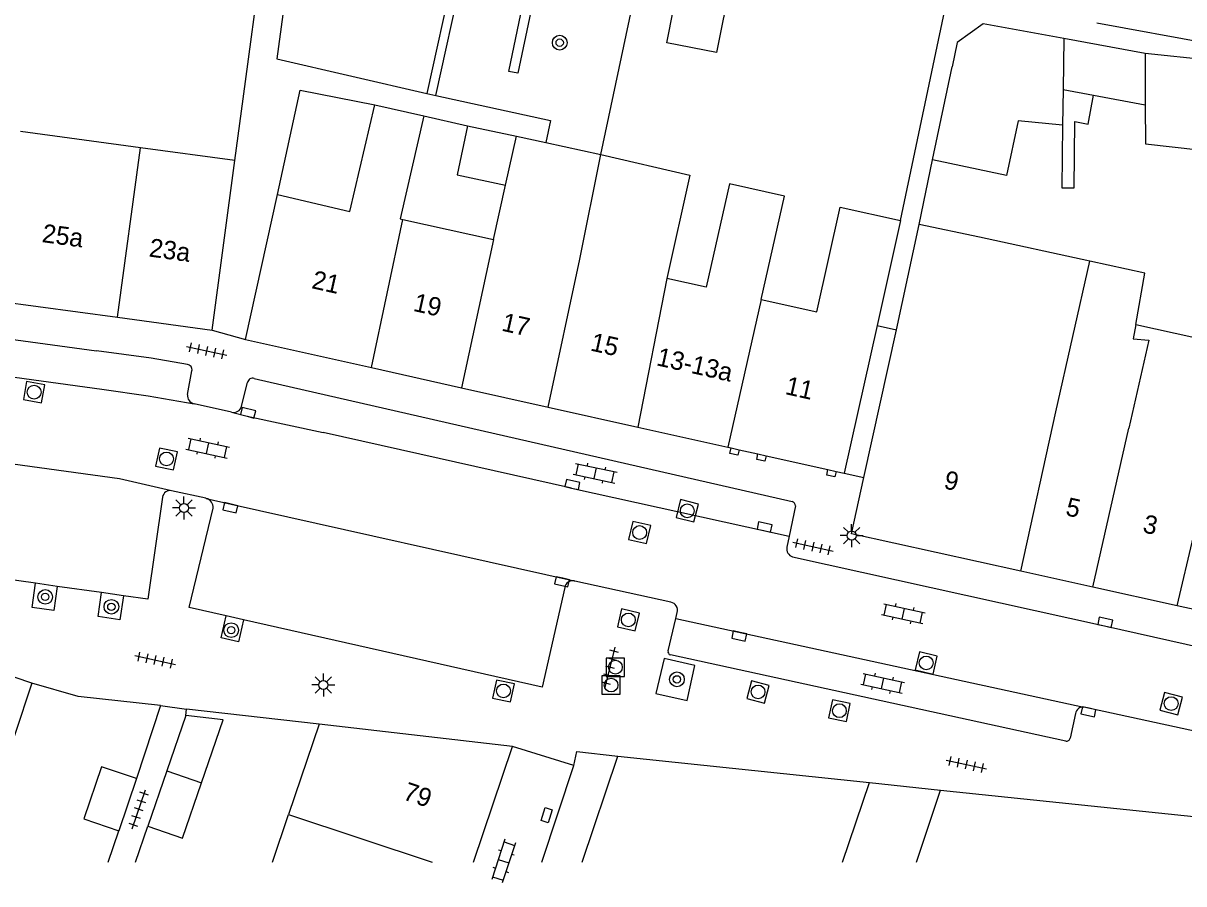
# Model space of a CAD drawing. Extents: x 132999 to 136000, y 398499 to 400501.
# Drawn here: x 133754.4 to 133817.5, y 398498.8 to 398545.6 of the extents above; entities that cross this region are included whole.
import ezdxf

# ---------------------------------------------------------------- set-up
doc = ezdxf.new("R2010")
doc.units = 0
for name, color, linetype in [('gg-afsc-erfafscheiding', 7, 'Continuous'), ('gg-afsc-hekwerk', 7, 'Continuous'), ('gg-afsc-muur', 7, 'Continuous'), ('gg-anno-huisnummerreeks BGT', 7, 'Continuous'), ('gg-bbg-bijgebouw', 7, 'Continuous'), ('gg-bbg-gedigitaliseerde bebouwing', 7, 'Continuous'), ('gg-bbg-gedigitaliseerde bebouwing onder overbouw', 7, 'Continuous'), ('gg-bbg-gedigitaliseerde bijgebouw', 7, 'Continuous'), ('gg-bbg-gedigitaliseerde overbouw', 7, 'Continuous'), ('gg-bbg-hoofdgebouw', 7, 'Continuous'), ('gg-bbg-luifel en loopbrug', 7, 'Continuous'), ('gg-bbg-pand overbouw', 7, 'Continuous'), ('gg-bbg-tussenscheiding', 7, 'Continuous'), ('gg-knt-verharding', 7, 'Continuous'), ('gg-knt-verharding nz', 7, 'Continuous'), ('gt-grn-groengrens', 7, 'Continuous'), ('gt-grn-weggrens', 7, 'Continuous'), ('gt-symb-boom', 7, 'Continuous'), ('gt-symb-klinker verharding', 7, 'Continuous'), ('gt-symb-kolk', 7, 'Continuous'), ('gt-symb-kolk center center', 7, 'Continuous'), ('gt-symb-lichtmast', 7, 'Continuous'), ('gt-symb-rioolschacht', 7, 'Continuous'), ('gt-symb-tegel verharding', 7, 'Continuous')]:
    doc.layers.add(name, color=color, linetype=linetype)

# ---------------------------------------------------------------- blocks, each defined once
blk = doc.blocks.new('gt0-BOOM')
at = {"layer": 'gt-symb-boom'}
for radius in [0.4, 0.2]:
    blk.add_circle((0, 0), radius, dxfattribs=at)
blk = doc.blocks.new('gt0-TEG1')
at = {"layer": 'gt-symb-tegel verharding'}
for p, q in [((-1.125, 0), (1.125, 0)), ((-0.9, -0.25), (-0.9, 0.25)), ((-0.45, -0.25), (-0.45, 0.25)), ((0, -0.25), (0, 0.25)), ((0.45, -0.25), (0.45, 0.25)), ((0.9, -0.25), (0.9, 0.25))]:
    blk.add_line(p, q, dxfattribs=at)
blk = doc.blocks.new('gt0-RS')
at = {"layer": 'gt-symb-rioolschacht'}
blk.add_lwpolyline([(-0.5, -0.5), (0.5, -0.5), (0.5, 0.5), (-0.5, 0.5)], close=True, dxfattribs=at)
blk.add_circle((0, 0), 0.375, dxfattribs=at)
blk = doc.blocks.new('gt0-KOLK')
at = {"layer": 'gt-symb-kolk'}
blk.add_lwpolyline([(0, 0), (0.375, 0), (0.375, 0.4), (-0.375, 0.4), (-0.375, 0), (0, 0)], dxfattribs=at)
blk = doc.blocks.new('gt0-KL1')
at = {"layer": 'gt-symb-klinker verharding'}
for p, q in [((-1.15, 0.3), (1.15, 0.3)), ((-1, -0.3), (-1, 0.3)), ((-0.5, 0.3), (-0.5, 0.45)), ((0, -0.3), (0, 0.3)), ((0.5, 0.3), (0.5, 0.45)), ((1, -0.3), (1, 0.3)), ((-1.15, -0.3), (1.15, -0.3)), ((-0.5, -0.45), (-0.5, -0.3)), ((0.5, -0.45), (0.5, -0.3))]:
    blk.add_line(p, q, dxfattribs=at)
blk = doc.blocks.new('gt0-LMAST')
at = {"layer": 'gt-symb-lichtmast'}
for p, q in [((-0.182, 0.173), (-0.447, 0.438)), ((-0.005, 0.246), (-0.005, 0.621)), ((0.172, 0.173), (0.437, 0.438)), ((-0.255, -0.004), (-0.63, -0.004)), ((-0.182, -0.181), (-0.447, -0.446)), ((-0.005, -0.254), (-0.005, -0.629)), ((0.437, -0.446), (0.172, -0.181)), ((0.245, -0.004), (0.62, -0.004))]:
    blk.add_line(p, q, dxfattribs=at)
blk.add_circle((-0.005, -0.004), 0.25, dxfattribs=at)
blk = doc.blocks.new('gt0-KOLKCC')
at = {"layer": 'gt-symb-kolk center center'}
blk.add_lwpolyline([(-0.375, 0.2), (0.375, 0.2), (0.375, -0.2), (-0.375, -0.2)], close=True, dxfattribs=at)

msp = doc.modelspace()

# ---------------------------------------------------------------- linework, layer by layer
at = {"layer": 'gg-afsc-erfafscheiding'}
for p, q in [((133785.848, 398538.479), (133788.011, 398548.694)), ((133802.141, 398534.88), (133804.709, 398547.134)), ((133812.811, 398545.642), (133819.826, 398544.351)), ((133803.143, 398534.665), (133803.88, 398538.181)), ((133761.902, 398508.507), (133760.593, 398504.543)), ((133763.284, 398507.975), (133763.315, 398508.313)), ((133759.054, 398500), (133759.631, 398501.701)), ((133760.549, 398500), (133761.208, 398501.943))]:
    msp.add_line(p, q, dxfattribs=at)
for points in [[(133765.944, 398538.153), (133766.393, 398541.509), (133767.437, 398549.211)], [(133768.258, 398536.304), (133769.488, 398541.979), (133773.557, 398541.183)]]:
    msp.add_lwpolyline(points, dxfattribs=at)
at = {"layer": 'gg-afsc-hekwerk'}
for p, q in [((133761.902, 398508.507), (133763.315, 398508.313)), ((133800.45, 398504.328), (133804.313, 398503.901))]:
    msp.add_line(p, q, dxfattribs=at)
at = {"layer": 'gg-afsc-muur'}
for p, q in [((133776.212, 398540.576), (133778.6, 398540.037)), ((133770.521, 398507.502), (133763.315, 398508.313))]:
    msp.add_line(p, q, dxfattribs=at)
msp.add_lwpolyline([(133761.902, 398508.507), (133757.421, 398508.992), (133754.914, 398509.721)], dxfattribs=at)
at = {"layer": 'gg-bbg-bijgebouw'}
for p, q in [((133763.284, 398507.975), (133762.246, 398504.959)), ((133784.826, 398500), (133786.769, 398505.747)), ((133786.769, 398505.747), (133800.45, 398504.328)), ((133762.246, 398504.959), (133761.208, 398501.943)), ((133760.593, 398504.543), (133759.631, 398501.701)), ((133798.989, 398500), (133800.45, 398504.328))]:
    msp.add_line(p, q, dxfattribs=at)
for points in [[(133764.133, 398504.313), (133765.303, 398507.728), (133763.284, 398507.975)], [(133760.593, 398504.543), (133758.699, 398505.184), (133757.737, 398502.342), (133759.631, 398501.701)], [(133761.208, 398501.943), (133763.099, 398501.292), (133764.133, 398504.313)]]:
    msp.add_lwpolyline(points, dxfattribs=at)
at = {"layer": 'gg-bbg-gedigitaliseerde bebouwing'}
for p, q in [((133760.816, 398538.843), (133754.295, 398539.721)), ((133765.944, 398538.153), (133760.816, 398538.843)), ((133785.848, 398538.479), (133790.686, 398537.36)), ((133764.71, 398528.931), (133765.944, 398538.153)), ((133790.686, 398537.36), (133789.428, 398531.737)), ((133780.001, 398533.844), (133780.664, 398536.81)), ((133775.08, 398534.945), (133780.001, 398533.844)), ((133802.141, 398534.88), (133800.867, 398529.179)), ((133801.923, 398528.943), (133803.143, 398534.665)), ((133814.922, 398529.225), (133818.147, 398528.527))]:
    msp.add_line(p, q, dxfattribs=at)
for points in [[(133776.212, 398540.576), (133774.932, 398534.979), (133775.08, 398534.945)], [(133794.556, 398530.59), (133795.827, 398536.211), (133792.839, 398536.879), (133791.568, 398531.258), (133789.428, 398531.737)], [(133794.556, 398530.59), (133797.579, 398529.914), (133798.854, 398535.615), (133802.141, 398534.88)], [(133812.432, 398532.678), (133806.434, 398533.975), (133803.143, 398534.665)], [(133814.922, 398529.225), (133815.427, 398532.031), (133812.432, 398532.678)]]:
    msp.add_lwpolyline(points, dxfattribs=at)
at = {"layer": 'gg-bbg-gedigitaliseerde bebouwing onder overbouw'}
for p, q in [((133800.867, 398529.179), (133799.07, 398521.141)), ((133800.148, 398520.903), (133801.923, 398528.943))]:
    msp.add_line(p, q, dxfattribs=at)
at = {"layer": 'gg-bbg-gedigitaliseerde bijgebouw'}
for p, q in [((133815.435, 398543.966), (133811.009, 398544.781)), ((133803.88, 398538.181), (133804.941, 398543.243)), ((133810.974, 398542.007), (133810.949, 398540.062)), ((133810.974, 398542.007), (133812.63, 398541.702)), ((133812.63, 398541.702), (133815.446, 398541.183))]:
    msp.add_line(p, q, dxfattribs=at)
for points in [[(133792.886, 398547.833), (133792.13, 398544.015), (133789.424, 398544.545), (133790.179, 398548.311)], [(133811.009, 398544.781), (133806.622, 398545.589), (133805.22, 398544.574), (133804.941, 398543.243)], [(133818.358, 398538.736), (133818.896, 398543.602), (133815.435, 398543.966)], [(133815.446, 398541.183), (133815.455, 398539.057), (133818.358, 398538.736)], [(133810.949, 398540.062), (133808.527, 398540.314), (133807.903, 398537.338), (133803.88, 398538.181)], [(133778.6, 398540.037), (133778.028, 398537.376), (133780.664, 398536.81)]]:
    msp.add_lwpolyline(points, dxfattribs=at)
at = {"layer": 'gg-bbg-gedigitaliseerde overbouw'}
msp.add_line((133800.867, 398529.179), (133801.923, 398528.943), dxfattribs=at)
at = {"layer": 'gg-bbg-hoofdgebouw'}
for p, q in [((133773.557, 398541.183), (133776.212, 398540.576)), ((133778.6, 398540.037), (133781.258, 398539.466)), ((133781.258, 398539.466), (133782.853, 398539.123)), ((133782.853, 398539.123), (133785.848, 398538.479)), ((133766.52, 398528.421), (133768.258, 398536.304)), ((133753.072, 398530.501), (133759.573, 398529.624)), ((133759.573, 398529.624), (133764.71, 398528.931)), ((133766.52, 398528.421), (133773.375, 398526.888)), ((133773.375, 398526.888), (133778.268, 398525.794)), ((133778.268, 398525.794), (133782.987, 398524.738)), ((133782.987, 398524.738), (133787.849, 398523.651)), ((133787.849, 398523.651), (133792.74, 398522.557)), ((133792.74, 398522.557), (133792.922, 398522.516)), ((133792.922, 398522.516), (133793.361, 398522.418)), ((133793.361, 398522.418), (133794.386, 398522.189)), ((133794.386, 398522.189), (133794.825, 398522.091)), ((133794.825, 398522.091), (133798.192, 398521.337)), ((133798.192, 398521.337), (133798.631, 398521.239)), ((133798.631, 398521.239), (133799.07, 398521.141)), ((133812.593, 398514.944), (133808.67, 398515.81)), ((133817.177, 398513.932), (133812.593, 398514.944)), ((133754.914, 398509.721), (133745.124, 398513.029)), ((133754.914, 398509.721), (133753.036, 398504.14)), ((133770.521, 398507.502), (133768.867, 398502.587)), ((133781.035, 398506.282), (133770.521, 398507.502)), ((133778.915, 398500), (133781.035, 398506.282)), ((133803, 398500), (133804.313, 398503.901)), ((133804.313, 398503.901), (133822.056, 398502.068)), ((133767.997, 398500), (133768.867, 398502.587))]:
    msp.add_line(p, q, dxfattribs=at)
for points in [[(133768.258, 398536.304), (133772.198, 398535.367), (133773.557, 398541.183)], [(133808.67, 398515.81), (133799.47, 398517.841), (133800.148, 398520.903)], [(133825.33, 398512.221), (133818.27, 398513.691), (133817.177, 398513.932)]]:
    msp.add_lwpolyline(points, dxfattribs=at)
at = {"layer": 'gg-bbg-luifel en loopbrug'}
msp.add_lwpolyline([(133810.949, 398540.062), (133810.907, 398536.665), (133811.578, 398536.656), (133811.623, 398540.265), (133812.341, 398540.132), (133812.63, 398541.702)], dxfattribs=at)
at = {"layer": 'gg-bbg-pand overbouw'}
msp.add_line((133799.07, 398521.141), (133800.148, 398520.903), dxfattribs=at)
at = {"layer": 'gg-bbg-tussenscheiding'}
for p, q in [((133811.009, 398544.781), (133810.974, 398542.007)), ((133815.435, 398543.966), (133815.446, 398541.183)), ((133780.664, 398536.81), (133781.258, 398539.466)), ((133759.573, 398529.624), (133760.816, 398538.843)), ((133773.375, 398526.888), (133775.08, 398534.945)), ((133780.001, 398533.844), (133778.268, 398525.794)), ((133810.582, 398524.473), (133812.432, 398532.678)), ((133789.428, 398531.737), (133787.849, 398523.651)), ((133794.556, 398530.59), (133792.74, 398522.557)), ((133808.67, 398515.81), (133810.582, 398524.473)), ((133812.593, 398514.944), (133814.559, 398523.594)), ((133817.177, 398513.932), (133819.205, 398522.588)), ((133762.246, 398504.959), (133764.133, 398504.313)), ((133768.867, 398502.587), (133776.669, 398500))]:
    msp.add_line(p, q, dxfattribs=at)
for points in [[(133782.987, 398524.738), (133784.709, 398532.792), (133785.848, 398538.479)], [(133814.922, 398529.225), (133814.782, 398528.449), (133815.646, 398528.373), (133814.559, 398523.594)]]:
    msp.add_lwpolyline(points, dxfattribs=at)
at = {"layer": 'gg-knt-verharding'}
for p, q in [((133776.382, 398541.793), (133776.87, 398541.683)), ((133763.377, 398525.415), (133763.611, 398526.71)), ((133767, 398526.29), (133796.246, 398519.609)), ((133766.315, 398524.782), (133766.642, 398526.074)), ((133765.769, 398524.458), (133763.727, 398524.923)), ((133764.373, 398519.781), (133762.509, 398520.194)), ((133764.373, 398519.781), (133764.39, 398519.777)), ((133796.423, 398519.368), (133796.084, 398517.714)), ((133796.084, 398517.714), (133795.961, 398517.115)), ((133756.283, 398514.989), (133755.11, 398515.155)), ((133758.702, 398514.648), (133756.283, 398514.989)), ((133784.435, 398515.277), (133784.396, 398515.286)), ((133789.654, 398514.131), (133784.435, 398515.277)), ((133759.885, 398514.481), (133758.702, 398514.648)), ((133766.416, 398513.175), (133765.478, 398513.387)), ((133789.498, 398511.491), (133789.916, 398513.248)), ((133789.916, 398513.248), (133789.992, 398513.567)), ((133811.127, 398506.577), (133789.631, 398511.259)), ((133811.653, 398508.07), (133811.354, 398506.729)), ((133826.534, 398505.282), (133812.111, 398508.423)), ((133784.384, 398505.246), (133781.035, 398506.282)), ((133782.63, 398500), (133784.384, 398505.246))]:
    msp.add_line(p, q, dxfattribs=at)
for points in [[(133782.245, 398549.718), (133769.355, 398551.993), (133768.22, 398543.678), (133776.382, 398541.793)], [(133776.87, 398541.683), (133783.109, 398540.316), (133782.853, 398539.123)], [(133720.867, 398531.313), (133721.073, 398532.895), (133758.42, 398527.801)], [(133763.366, 398527.06), (133761.397, 398527.395), (133758.42, 398527.801)], [(133793.361, 398522.418), (133793.296, 398522.125), (133792.856, 398522.224), (133792.922, 398522.516)], [(133755.11, 398515.155), (133746.922, 398516.31), (133747.725, 398522.032)], [(133794.825, 398522.091), (133794.759, 398521.798), (133794.32, 398521.896), (133794.386, 398522.189)], [(133798.631, 398521.239), (133798.565, 398520.946), (133798.126, 398521.045), (133798.192, 398521.337)], [(133762.015, 398519.846), (133761.206, 398514.295), (133759.885, 398514.481)], [(133765.478, 398513.387), (133763.459, 398513.842), (133764.76, 398519.238)], [(133796.261, 398516.597), (133813.224, 398512.839), (133826.382, 398509.897), (133827.455, 398509.674)], [(133756.283, 398514.989), (133756.097, 398513.673), (133754.925, 398513.843), (133755.11, 398515.155)], [(133783.885, 398514.929), (133782.65, 398509.516), (133766.416, 398513.175)], [(133759.885, 398514.481), (133759.7, 398513.173), (133758.518, 398513.346), (133758.702, 398514.648)], [(133766.416, 398513.175), (133766.147, 398511.982), (133765.207, 398512.184), (133765.478, 398513.387)], [(133789.289, 398511.063), (133788.836, 398509.163), (133790.541, 398508.78), (133790.951, 398510.682), (133789.289, 398511.063)], [(133784.384, 398505.246), (133784.534, 398506.002), (133786.769, 398505.747)]]:
    msp.add_lwpolyline(points, dxfattribs=at)
for centre, radius, start, end in [((133763.327, 398526.772), 0.29, 347.65134, 82.3327), ((133766.901, 398526.05), 0.26, 67.56084, 174.64868), ((133763.811, 398525.353), 0.439, 171.93122, 258.92351), ((133765.87, 398524.911), 0.464, 257.47953, 343.89081), ((133762.437, 398519.772), 0.428, 80.25882, 170.067), ((133764.267, 398519.296), 0.496, 353.25373, 75.68207), ((133796.18, 398519.375), 0.243, 358.27938, 74.3107), ((133796.392, 398517.019), 0.441, 167.38529, 252.76932), ((133784.317, 398514.854), 0.439, 79.66645, 170.21217), ((133789.564, 398513.694), 0.446, 343.50896, 78.35878), ((133789.685, 398511.444), 0.193, 166.0107, 253.63851), ((133812.059, 398508.017), 0.41, 82.74055, 172.50538), ((133811.172, 398506.755), 0.183, 255.66594, 351.94687)]:
    msp.add_arc(centre, radius, start, end, dxfattribs=at)
at = {"layer": 'gg-knt-verharding nz'}
for p, q in [((133741.118, 398528.107), (133758.721, 398525.714)), ((133784.257, 398520.335), (133770.746, 398523.352)), ((133784.257, 398520.335), (133796.084, 398517.714)), ((133789.916, 398513.248), (133812.111, 398508.423))]:
    msp.add_line(p, q, dxfattribs=at)
for points in [[(133758.721, 398525.714), (133761.228, 398525.345), (133763.727, 398524.923)], [(133765.769, 398524.458), (133766.614, 398524.237), (133770.746, 398523.352)], [(133762.509, 398520.194), (133759.683, 398520.831), (133749.505, 398522.227), (133747.32, 398522.55)], [(133764.39, 398519.777), (133765.74, 398519.461), (133784.396, 398515.286)]]:
    msp.add_lwpolyline(points, dxfattribs=at)
at = {"layer": 'gt-grn-groengrens'}
for points in [[(133782.737, 398549.631), (133781.332, 398542.896), (133780.842, 398542.998), (133782.245, 398549.718)], [(133776.87, 398541.683), (133778.297, 398548.2), (133777.809, 398548.306), (133776.382, 398541.793)]]:
    msp.add_lwpolyline(points, dxfattribs=at)
at = {"layer": 'gt-grn-weggrens'}
msp.add_line((133764.71, 398528.931), (133766.52, 398528.421), dxfattribs=at)

# ---------------------------------------------------------------- block references
at = {"layer": 'gt-symb-boom'}
for p in [(133783.607, 398544.557), (133755.636, 398514.418), (133759.232, 398513.879), (133765.744, 398512.609), (133789.98, 398509.933)]:
    msp.add_blockref('gt0-BOOM', p, dxfattribs=at)
at = {"layer": 'gt-symb-klinker verharding'}
for p, rotation in [((133764.476, 398522.508), -12.298855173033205), ((133785.536, 398521.141), -12.174751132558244), ((133802.286, 398513.502), -12.41077472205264), ((133801.165, 398509.718), -12.410774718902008), ((133780.554, 398500.048), -108.18126897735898)]:
    msp.add_blockref('gt0-KL1', p, dxfattribs=dict(at, rotation=rotation))
at = {"layer": 'gt-symb-kolk'}
for p, rotation in [((133766.614, 398524.237), -14.66187016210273), ((133784.257, 398520.335), -12.479071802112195), ((133765.74, 398519.461), 166.82507339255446), ((133794.702, 398518.02), -12.493796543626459), ((133783.774, 398515.428), 167.40904938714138), ((133813.224, 398512.839), -12.49379654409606), ((133793.413, 398512.487), 167.72939792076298), ((133812.398, 398508.36), 167.72151291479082)]:
    msp.add_blockref('gt0-KOLK', p, dxfattribs=dict(at, rotation=rotation))
at = {"layer": 'gt-symb-kolk center center', "rotation": -107.94556305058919}
msp.add_blockref('gt0-KOLKCC', (133782.897, 398502.551), dxfattribs=at)
at = {"layer": 'gt-symb-lichtmast'}
for p in [(133763.185, 398519.257), (133799.484, 398517.756), (133770.762, 398509.633)]:
    msp.add_blockref('gt0-LMAST', p, dxfattribs=at)
at = {"layer": 'gt-symb-rioolschacht'}
for p, rotation in [((133755.032, 398525.549), -9.96151659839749), ((133762.232, 398521.918), -101.95064726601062), ((133790.543, 398519.099), 165.78174773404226), ((133787.954, 398517.916), -12.938810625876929), ((133787.34, 398513.164), -12.827123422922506), ((133803.535, 398510.825), 166.47068167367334), ((133780.549, 398509.303), -12.062746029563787), ((133794.392, 398509.249), -14.952208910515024), ((133798.815, 398508.229), -12.015845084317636), ((133816.853, 398508.614), 165.49013525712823)]:
    msp.add_blockref('gt0-RS', p, dxfattribs=dict(at, rotation=rotation))
for p in [(133786.637, 398510.594), (133786.401, 398509.623)]:
    msp.add_blockref('gt0-RS', p, dxfattribs=at)
at = {"layer": 'gt-symb-tegel verharding'}
for p, rotation in [((133764.419, 398527.794), -12.29885516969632), ((133797.38, 398517.146), -12.410774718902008), ((133761.615, 398510.982), -12.29885516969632), ((133786.352, 398510.585), 76.06098564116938), ((133805.72, 398505.302), -12.410774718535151), ((133760.728, 398502.863), 71.45633066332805)]:
    msp.add_blockref('gt0-TEG1', p, dxfattribs=dict(at, rotation=rotation))

# ---------------------------------------------------------------- texts
at = {"layer": 'gg-anno-huisnummerreeks BGT'}
for s, rotation, p in [('25a', 352.3, (133755.425, 398533.716)), ('23a', 352.3, (133761.244, 398532.931)), ('21', 347.4, (133770.075, 398531.212)), ('19', 347.4, (133775.597, 398529.977)), ('17', 347.4, (133780.4, 398528.903)), ('15', 347.4, (133785.229, 398527.823)), ('13-13a', 347.4, (133788.818, 398527.02)), ('11', 347.4, (133795.82, 398525.454)), ('9', 347.5, (133804.445, 398520.327)), ('5', 347.5, (133811.064, 398518.866)), ('3', 347.5, (133815.26, 398517.94)), ('79', 341.3, (133775.028, 398503.422))]:
    msp.add_text(s, height=1, rotation=rotation, dxfattribs=at).set_placement(p)

doc.saveas('drawing.dxf')
